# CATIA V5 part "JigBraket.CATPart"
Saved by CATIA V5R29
Part number: JigBraket
Source: Unknown
Bounding box of the stored display mesh (mm): x -25 to 25, y -30 to 30, z -50 to 15
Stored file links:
  C:\가치같이\SmartFactory_BoxErectorConveyor\Boxing(under)\JigBraket.CATPart
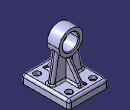
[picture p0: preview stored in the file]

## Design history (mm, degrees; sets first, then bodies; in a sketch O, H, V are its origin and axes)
Body1 (main body)
  Solid1 "PartBody": solid without history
